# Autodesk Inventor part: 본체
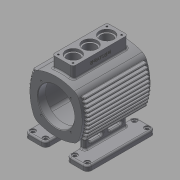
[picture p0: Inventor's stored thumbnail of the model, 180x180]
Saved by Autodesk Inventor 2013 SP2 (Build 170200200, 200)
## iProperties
Created: 2015-11
Part Number: 본체
Material: 일반
Document SubType Name: Modeling
Designer: mduedu
Density: 1 g/cm^3
Author: mduedu
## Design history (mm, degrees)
sketch "스케치2"
  geometry: L1 (0, 250)-(0, -250); L2 (250, 0)-(-250, 0); L3 (-50, 50)-(50, 50); L4 (50, 50)-(50, -50); L5 (50, -50)-(-50, -50); L6 (-50, -50)-(-50, 50); A1 r 90 centre (-40, 0) between (40.415, -40.415) and (40.415, 40.415); A2 r 90 centre (40, 0) between (-40.415, 40.415) and (-40.415, -40.415); A3 r 90 centre (0, -40) between (40.415, 40.415) and (-40.415, 40.415); A4 r 90 centre (0, 40) between (-40.415, -40.415) and (40.415, -40.415); 2 further points
  constraints: 12 end point, 8 point on circle, 4 centre point, 4 tangent, 3 perpendicular, 2 horizontal alignment, 2 midpoint, 2 parallel, 2 symmetric about line, 1 coincident, 1 equal radius, 1 horizontal, 1 vertical, 1 vertical alignment, 2 other
  dimensions: "d6" = 500 distance of L1.start L1.end; "d8" = 500 distance of L2.start L2.end; "d9" = 100 distance of L3.end L4.end; "d11" = 90 radius of A3
extrude "돌출1" new body sketch "스케치2" stored distance "d12" = 130; taper "d13" = 0 deg
sketch "스케치3"
  geometry: A1 r 90 centre (40, 0) between (-40.415, 40.415) and (-40.415, -40.415) reference; 2 further points
  constraints: 1 point on circle
fillet "모깎기6" dims "d30" = 15
feature "쉘1" dims "d31" = 15, "d32" = 6, "d33" = 15
sketch "스케치4"
  geometry: L1 (60, -57)-(-60, -57); L2 (-65, 40.415)-(-65, -40.415) reference; L3 (65, -40.415)-(65, 40.415) reference; L4 (-60, -57)-(-60, -45); L5 (60, -57)-(60, -45); L6 (-65, -50)-(65, -50) reference; L7 (-60, -45)-(60, -45); 2 further points
  constraints: 8 end point, 2 parallel, 1 horizontal
  dimensions: "d16" = 5 distance between parallel lines of L7 L6; "d17" = 12 distance of L1.start L5.end; "d23" = 5 distance between parallel lines of L4 L2; "d24" = 5 distance between parallel lines of L5 L3
extrude "돌출2" new body sketch "스케치4" stored distance "d18" = 3; taper "d19" = 0 deg
fillet "모깎기1" dims "d20" = 3
fillet "모깎기4" dims "d25" = 1
sketch "스케치5"
  geometry: C1 r 35 at (0, 0); 1 further point
  constraints: 1 centre point, 1 coincident
  dimensions: "d34" = 70 diameter of C1
extrude "돌출3" cut sketch "스케치5" stored distance "d36" = 3; taper "d37" = 0 deg
feature "결합1"
  node "솔리드2"
fillet "모깎기7" dims "d38" = 1
fillet "모깎기8" dims "d39" = 1
node "작업 평면1"
sketch "스케치6"
  geometry: L1 (-65, -60)-(65, -60); L2 (65, -60)-(65, 60); L3 (65, 60)-(-65, 60); L4 (-65, 60)-(-65, -60); L5 (-65, -60)-(65, 60); L6 (65, -60)-(-65, 60); 1 further point
  constraints: 12 end point, 2 midpoint, 2 parallel, 1 horizontal, 1 perpendicular
  dimensions: "d41" = 120 distance of L3.end L1.start; "d43" = 130 distance of L2.end L3.end
extrude "돌출4" join sketch "스케치6" distance "d44" = 10; taper "d45" = 0 deg
sketch "스케치8"
  geometry: L1 (-60, -70)-(60, -70) reference; L2 (0, -50)-(0, -70); L3 (-30, -44.853)-(-30, -70); L4 (30, -44.853)-(30, -70); L5 (-30, -70)-(30, -70); A1 r 90 centre (0, 40) between (-34.941, -42.941) and (34.941, -42.941) reference; A2 r 90 centre (0, 40) between (-30, -44.853) and (30, -44.853); 1 further point
  constraints: 8 end point, 5 point on circle, 2 perpendicular, 2 symmetric about line, 1 centre point, 1 midpoint, 1 point on line
  dimensions: "d48" = 60 distance between parallel lines of L4 L3
extrude "돌출5" join sketch "스케치8" stored distance "d50" = 80; taper "d51" = 0 deg
sketch "스케치9"
  geometry: L1 (-30, -44.853)-(-30, -70) reference; L2 (30, -70)-(30, -44.853) reference; L3 (-20, -47.75)-(-20, -80); L4 (20, -80)-(20, -47.75); L5 (-48.917, -80)-(48.917, -80) reference; A1 r 90 centre (0, 40) between (-34.941, -42.941) and (34.941, -42.941) reference; 1 further point
  constraints: 4 end point, 2 parallel, 2 point on circle, 2 point on line
  dimensions: "d52" = 10 distance between parallel lines of L2 L4; "d54" = 10 distance between parallel lines of L1 L3 (derived)
extrude "돌출6" cut sketch "스케치9" stored distance "d55" = 80; taper "d56" = 0 deg
fillet "모깎기9" dims "d57" = 8
sketch "스케치10"
  geometry: A1 r 8 centre (-57, 52) between (-57, 60) and (-65, 52) reference; A2 r 8 centre (57, 52) between (65, 52) and (57, 60) reference; A3 r 8 centre (57, 28) between (57, 20) and (65, 28) reference; A4 r 8 centre (-57, 28) between (-65, 28) and (-57, 20) reference; A5 r 8 centre (-57, -28) between (-57, -20) and (-65, -28) reference; A6 r 8 centre (-57, -52) between (-65, -52) and (-57, -60) reference; A7 r 8 centre (57, -52) between (57, -60) and (65, -52) reference; A8 r 8 centre (57, -28) between (65, -28) and (57, -20) reference; 1 further point
hole "구멍1" sketch "스케치10" at (-57, 52), (57, 52), (57, 28), (-57, 28), (-57, -28), (-57, -52), (57, -52), (57, -28) diameter "d58" = 6; stored, may be unused: countersink angle "d62" = 90 deg, drill point angle "d64" = 118 deg; dims "d59" = 6, "d60" = 10, "d61" = 2, "d63" = 8
fillet "모깎기10" dims "d65" = 3
fillet "모깎기11" dims "d66" = 3
fillet "모깎기12" dims "d67" = 3
sketch "스케치11" dims "d72" = 25
  geometry: L1 (65, -50)-(-65, -50) reference; L2 (-80.5, -80)-(80.5, -80) reference; L3 (0, -50)-(0, -80); L4 (-27, -54)-(-10, -54); L5 (-10, -54)-(-10, -62); L6 (-10, -62)-(-27, -62); L7 (-27, -62)-(-27, -54); 3 further points
  constraints: 10 end point, 4 midpoint, 2 parallel, 2 perpendicular, 2 vertical alignment, 1 horizontal, 4 other
  dimensions: "d68" = 8 distance between parallel lines of L6 L4; "d71" = 8 distance from line of point (-27, -58) L1; "d73" = 6 dimension on L3
extrude "돌출7" cut sketch "스케치11" stored distance "d74" = 80; taper "d75" = 0 deg
fillet "모깎기13" dims "d76" = 3
fillet "모깎기14" dims "d78" = 3
sketch "스케치12"
  geometry: L1 (0, 0)-(28.284, 28.284); L2 (0, 0)-(40, 0); A1 r 40 centre (0, 0) between (28.284, 28.284) and (40, 0); 2 further points
  constraints: 4 end point, 2 coincident, 2 point on circle, 1 centre point, 1 horizontal
  dimensions: "d79" = 80 diameter of A1; "d80" = 45 deg angle of L2 L1
hole "구멍2" sketch "스케치12" at (28.284, 28.284) diameter "d82" = 3.242; stored, may be unused: countersink angle "d86" = 90 deg, drill point angle "d88" = 118 deg; dims "d83" = 9, "d84" = 10, "d85" = 2, "d87" = 11
node "작업 평면2"
sketch "스케치13"
  geometry: L1 (-52.5, -20)-(52.5, -20); L2 (52.5, -20)-(52.5, 20); L3 (52.5, 20)-(-52.5, 20); L4 (-52.5, 20)-(-52.5, -20); L5 (-52.5, -20)-(52.5, 20); L6 (52.5, -20)-(-52.5, 20); 1 further point
  constraints: 12 end point, 2 midpoint, 2 parallel, 1 horizontal, 1 perpendicular
  dimensions: "d93" = 105 distance of L2.end L3.end; "d95" = 40 distance of L1.end L2.end
extrude "돌출8" join sketch "스케치13" stored distance "d96" = 80; taper "d97" = 0 deg
fillet "모깎기15" dims "d98" = 5
fillet "모깎기16" dims "d99" = 3
sketch "스케치14"
  geometry: L1 (-52.5, 15)-(-52.5, -15) reference; L2 (52.5, -15)-(52.5, 15) reference; L3 (-52.5, 0)-(52.5, 0); 4 further points
  constraints: 2 end point, 2 midpoint, 2 point on line, 1 coincident
  dimensions: "d100" = 32 distance of point (-32, 0) point (0, 0); "d102" = 32 distance of point (32, 0) point (0, 0) (derived)
hole "구멍3" sketch "스케치14" at (-32, 0), (0, 0), (32, 0) diameter "d103" = 22; stored, may be unused: countersink angle "d107" = 90 deg, drill point angle "d109" = 118 deg; dims "d104" = 8, "d105" = 28, "d106" = 5, "d108" = 10
sketch "스케치15"
  geometry: L1 (46.5, -14)-(-46.5, -14); L2 (-46.5, -14)-(-46.5, 14); L3 (-46.5, 14)-(46.5, 14); L4 (46.5, 14)-(46.5, -14); L5 (46.5, -14)-(-46.5, 14); L6 (-46.5, -14)-(46.5, 14); L7 (47.5, 20)-(-47.5, 20) reference; L8 (-52.5, 15)-(-52.5, -15) reference; 5 further points
  constraints: 12 end point, 4 coincident, 2 midpoint, 2 parallel, 1 horizontal, 1 perpendicular
  dimensions: "d110" = 6 distance between parallel lines of L3 L7; "d111" = 6 distance between parallel lines of L2 L8
hole "구멍4" sketch "스케치15" at (-46.5, 14), (46.5, 14), (46.5, -14), (-46.5, -14) diameter "d112" = 3.242; stored, may be unused: countersink angle "d116" = 90 deg, drill point angle "d118" = 118 deg; dims "d113" = 10, "d114" = 28, "d115" = 5, "d117" = 13
sketch "스케치16"
  geometry: L1 (33.5, 0)-(61.5, 0) reference; L2 (104.5, -150)-(-9.5, -150) reference; L3 (47.5, 0)-(47.5, -150); 2 further points
  constraints: 2 end point, 2 midpoint, 1 point on line, 1 other
  dimensions: "d122" = 11 distance from line of point (47.5, -11) L1
feature "엠보싱2" sketch "스케치16" dims "d16" = 5, "d17" = 12, "d23" = 5, "d24" = 5, "d123" = 0.5, "d124" = 0
chamfer "모따기1" distance "d125" = 1; stored, may be unused: second distance "d126" = 2, angle "d127" = 45 deg
node "솔리드1"
pattern_linear "직사각형 패턴1" dims "d29" = 7
mirror "대칭1"
mirror "대칭2"
pattern_circular "원형 패턴1" dims angle "d90" = 360 deg
mirror "대칭3"
